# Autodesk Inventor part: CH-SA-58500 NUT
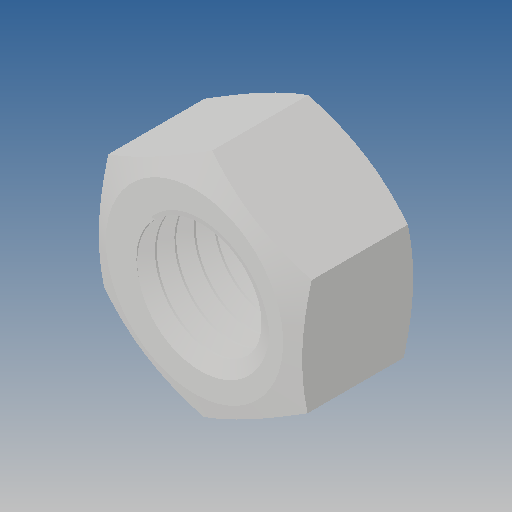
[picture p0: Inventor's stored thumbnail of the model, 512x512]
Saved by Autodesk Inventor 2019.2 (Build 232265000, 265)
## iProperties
Created: 2012-09
Part Number: CH-SA-58500 NUT
Material: Ogólny
Document SubType Name: Modeling
Designer: CADENGINEERING4
Density: 1 g/cm^3
Appearance: Domyślna
Author: CADENGINEERING4
Revision Number: ÈÎºÎ
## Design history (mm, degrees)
feature "ÇÐ³ý-É¨Ãè1"
node "Bryła1"
